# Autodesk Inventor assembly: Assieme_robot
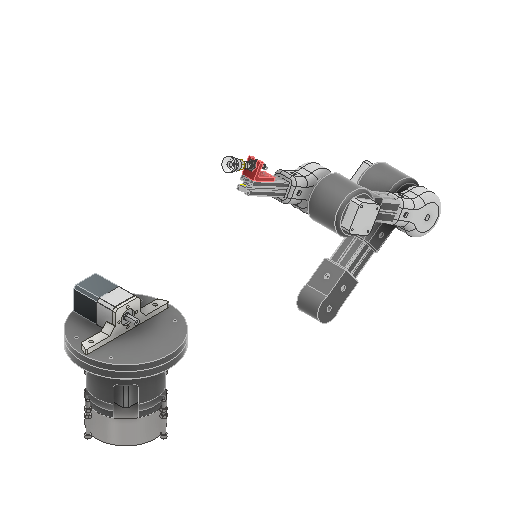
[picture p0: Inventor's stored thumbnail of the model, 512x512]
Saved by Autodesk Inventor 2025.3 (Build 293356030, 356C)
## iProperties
Created: 2026-03
Part Number: Assieme_robot
Document SubType Name: Assembly
Designer: R5800u
Author: R5800u
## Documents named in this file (19)
- C:\Users\R5800u\Desktop\robot_riduttore_cicloidale3\Workgroups\NotInProject\Assieme_robot.iam
- C:\Users\R5800u\Desktop\robot_riduttore_cicloidale3\Workgroups\NotInProject\riduttore_cicloidale_nema17-47mm.iam
- C:\Users\R5800u\Desktop\robot_riduttore_cicloidale3\Workgroups\NotInProject\braccio1.ipt
- C:\Users\R5800u\Desktop\robot_riduttore_cicloidale3\Workgroups\NotInProject\tslot-20x20-100mm.ipt
- C:\Users\R5800u\Desktop\robot_riduttore_cicloidale3\Workgroups\NotInProject\riduttore_cicloidale_nema17-40mm.iam
- C:\Users\R5800u\Desktop\robot_riduttore_cicloidale3\Workgroups\NotInProject\base_ferro.ipt
- C:\Users\R5800u\Desktop\robot_riduttore_cicloidale3\Workgroups\NotInProject\ISO 104 - 1 11 50 x 70 x 14.ipt
- C:\Users\R5800u\Desktop\robot_riduttore_cicloidale3\Workgroups\NotInProject\blocco_base.ipt
- C:\Users\R5800u\Desktop\robot_riduttore_cicloidale3\Workgroups\NotInProject\disco_base1.ipt
- C:\Users\R5800u\Desktop\robot_riduttore_cicloidale3\Workgroups\NotInProject\disco_base2.ipt
- C:\Users\R5800u\Desktop\robot_riduttore_cicloidale3\Workgroups\NotInProject\staffa_nema.ipt
- C:\Users\R5800u\Documents\Inventor\Content Center Files\R2025\it-IT\AS 1112 (2)\AS 1112 - M5  Tipo 5.ipt
- C:\Users\R5800u\Documents\Inventor\Content Center Files\R2025\it-IT\ANSI B18.3.1M(6)\ANSI B18.3.1M - M5x0,8 x 50(1).ipt
- C:\Users\R5800u\Desktop\robot_riduttore_cicloidale3\Workgroups\NotInProject\blocco_nema.ipt
- C:\Users\R5800u\Desktop\robot_riduttore_cicloidale3\Workgroups\NotInProject\blocco_albero_nema.ipt
- C:\Users\R5800u\Desktop\robot_riduttore_cicloidale3\Workgroups\NotInProject\ventosa_20mm.iam
- C:\Users\R5800u\Documents\Inventor\Content Center Files\R2025\it-IT\AS 1420\AS 1420 - 1973 - M3 x 16.ipt
- C:\Users\R5800u\Documents\Inventor\Content Center Files\R2025\it-IT\AS 1112 (2)\AS 1112 - M4  Tipo 5.ipt
- C:\Users\R5800u\Desktop\robot_riduttore_cicloidale3\Workgroups\NotInProject\Assieme_frame_tslot.iam
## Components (37 placed, 18 different names)
1. riduttore_cicloidale_nema17-47mm:1 [sub-assembly]
2. braccio1:1 — Coincidente:7, Angolo:1, Coincidente:10, Coincidente:11, Allineato:4, Coincidente:56, Coincidente:59
3. tslot-20x20-100mm:1 — Coincidente:10, Coincidente:11, Coincidente:37, Allineato:9, Coincidente:38, Coincidente:56, Coincidente:57, Coincidente:58
4. riduttore_cicloidale_nema17-40mm:1 [sub-assembly] — Coincidente:13, Allineato:3, Angolo:2, Coincidente:16, Coincidente:18
5. base_ferro:1
6. UNI ISO 104 1 11 50 x 70 x 14:1 — Coincidente:14, Coincidente:15
7. blocco_base:1
8. disco_base1:1 — Coincidente:16, Coincidente:17, Coincidente:19, Angolo:6
9. disco_base2:1 — Coincidente:18, Coincidente:19, Angolo:3, Coincidente:20
10. staffa_nema:1 — Coincidente:24, Coincidente:25, Allineato:6
11. AS 1112 (2) - Metrico M5  Tipo 5:5
12. AS 1112 (2) - Metrico M5  Tipo 5:6
13. AS 1112 (2) - Metrico M5  Tipo 5:7
14. AS 1112 (2) - Metrico M5  Tipo 5:8
15. Vite forgiata a testa incassata - Metrico M5x0,8 x 50:1 — Coincidente:30
16. Vite forgiata a testa incassata - Metrico M5x0,8 x 50:2 — Coincidente:32
17. Vite forgiata a testa incassata - Metrico M5x0,8 x 50:3 — Coincidente:34
18. Vite forgiata a testa incassata - Metrico M5x0,8 x 50:4 — Coincidente:36
19. blocco_nema:1 — Coincidente:37, Allineato:9, Coincidente:38, Coincidente:39, Angolo:4, Allineato:10, Coincidente:41
20. riduttore_cicloidale_nema17-40mm:2 [sub-assembly] — Coincidente:39, Angolo:4, Allineato:10, Coincidente:40
21. blocco_albero_nema:1 — Coincidente:40, Coincidente:41, Coincidente:42, Coincidente:43, Coincidente:44
22. tslot-20x20-100mm:2 — Coincidente:42, Coincidente:43, Coincidente:44, Coincidente:45, Allineato:11, Coincidente:46, Coincidente:60, Coincidente:61
23. blocco_nema:2 — Coincidente:45, Allineato:11, Coincidente:46, Coincidente:47, Angolo:5, Coincidente:48, Coincidente:50, Coincidente:62
24. riduttore_cicloidale_nema17-40mm:3 [sub-assembly] — Coincidente:47, Angolo:5, Coincidente:48, Coincidente:49
25. blocco_albero_nema:2 — Coincidente:49, Coincidente:50, Coincidente:51, Coincidente:52, Coincidente:53, Coincidente:55
26. ventosa_20mm:1 [sub-assembly] — Coincidente:51, Coincidente:52, Coincidente:53
27. AS 1420 - Metrico M3 x 16:1 — Coincidente:55
28. AS 1112 (2) - Metrico M4  Tipo 5:1
29. AS 1112 (2) - Metrico M4  Tipo 5:2
30. AS 1112 (2) - Metrico M4  Tipo 5:3
31. AS 1112 (2) - Metrico M4  Tipo 5:4
32. Assieme_frame_tslot:1 [sub-assembly] — Coincidente:57, Coincidente:58, Coincidente:59
33. Assieme_frame_tslot:2 [sub-assembly] — Coincidente:60, Coincidente:61, Coincidente:62
34. AS 1112 (2) - Metrico M5  Tipo 5:1
35. AS 1112 (2) - Metrico M5  Tipo 5:2
36. AS 1112 (2) - Metrico M5  Tipo 5:3
37. AS 1112 (2) - Metrico M5  Tipo 5:4
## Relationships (54: Mate 42, Angle 6, Flush 6)
- Coincidente:7 [Mate]: braccio1:1
- Angolo:1 [Angle]: braccio1:1
- Coincidente:10 [Mate]: braccio1:1 ↔ tslot-20x20-100mm:1
- Coincidente:11 [Mate]: braccio1:1 ↔ tslot-20x20-100mm:1
- Coincidente:13 [Mate]: riduttore_cicloidale_nema17-40mm:1
- Allineato:3 [Flush]: riduttore_cicloidale_nema17-40mm:1
- Coincidente:14 [Mate]: UNI ISO 104 1 11 50 x 70 x 14:1
- Coincidente:15 [Mate]: UNI ISO 104 1 11 50 x 70 x 14:1
- Angolo:2 [Angle]: riduttore_cicloidale_nema17-40mm:1
- Coincidente:16 [Mate]: riduttore_cicloidale_nema17-40mm:1 ↔ disco_base1:1
- Coincidente:17 [Mate]: disco_base1:1
- Coincidente:18 [Mate]: riduttore_cicloidale_nema17-40mm:1 ↔ disco_base2:1
- Coincidente:19 [Mate]: disco_base1:1 ↔ disco_base2:1
- Angolo:3 [Angle]: disco_base2:1
- Coincidente:20 [Mate]: disco_base2:1
- Allineato:4 [Flush]: braccio1:1
- Coincidente:24 [Mate]: staffa_nema:1
- Coincidente:25 [Mate]: staffa_nema:1
- Allineato:6 [Flush]: staffa_nema:1
- Coincidente:30 [Mate]: Vite forgiata a testa incassata - Metrico M5x0,8 x 50:1
- Coincidente:32 [Mate]: Vite forgiata a testa incassata - Metrico M5x0,8 x 50:2
- Coincidente:34 [Mate]: Vite forgiata a testa incassata - Metrico M5x0,8 x 50:3
- Coincidente:36 [Mate]: Vite forgiata a testa incassata - Metrico M5x0,8 x 50:4
- Coincidente:37 [Mate]: tslot-20x20-100mm:1 ↔ blocco_nema:1
- Allineato:9 [Flush]: tslot-20x20-100mm:1 ↔ blocco_nema:1
- Coincidente:38 [Mate]: tslot-20x20-100mm:1 ↔ blocco_nema:1
- Coincidente:39 [Mate]: blocco_nema:1 ↔ riduttore_cicloidale_nema17-40mm:2
- Angolo:4 [Angle]: blocco_nema:1 ↔ riduttore_cicloidale_nema17-40mm:2
- Allineato:10 [Flush]: blocco_nema:1 ↔ riduttore_cicloidale_nema17-40mm:2
- Coincidente:40 [Mate]: riduttore_cicloidale_nema17-40mm:2 ↔ blocco_albero_nema:1
- Coincidente:41 [Mate]: blocco_nema:1 ↔ blocco_albero_nema:1
- Coincidente:42 [Mate]: blocco_albero_nema:1 ↔ tslot-20x20-100mm:2
- Coincidente:43 [Mate]: blocco_albero_nema:1 ↔ tslot-20x20-100mm:2
- Coincidente:44 [Mate]: blocco_albero_nema:1 ↔ tslot-20x20-100mm:2
- Coincidente:45 [Mate]: tslot-20x20-100mm:2 ↔ blocco_nema:2
- Allineato:11 [Flush]: tslot-20x20-100mm:2 ↔ blocco_nema:2
- Coincidente:46 [Mate]: tslot-20x20-100mm:2 ↔ blocco_nema:2
- Coincidente:47 [Mate]: blocco_nema:2 ↔ riduttore_cicloidale_nema17-40mm:3
- Angolo:5 [Angle]: blocco_nema:2 ↔ riduttore_cicloidale_nema17-40mm:3
- Coincidente:48 [Mate]: blocco_nema:2 ↔ riduttore_cicloidale_nema17-40mm:3
- Coincidente:49 [Mate]: riduttore_cicloidale_nema17-40mm:3 ↔ blocco_albero_nema:2
- Coincidente:50 [Mate]: blocco_nema:2 ↔ blocco_albero_nema:2
- Coincidente:51 [Mate]: blocco_albero_nema:2 ↔ ventosa_20mm:1
- Coincidente:52 [Mate]: blocco_albero_nema:2 ↔ ventosa_20mm:1
- Coincidente:53 [Mate]: blocco_albero_nema:2 ↔ ventosa_20mm:1
- Coincidente:55 [Mate]: blocco_albero_nema:2 ↔ AS 1420 - Metrico M3 x 16:1
- Angolo:6 [Angle]: disco_base1:1
- Coincidente:56 [Mate]: braccio1:1 ↔ tslot-20x20-100mm:1
- Coincidente:57 [Mate]: tslot-20x20-100mm:1 ↔ Assieme_frame_tslot:1
- Coincidente:58 [Mate]: tslot-20x20-100mm:1 ↔ Assieme_frame_tslot:1
- Coincidente:59 [Mate]: braccio1:1 ↔ Assieme_frame_tslot:1
- Coincidente:60 [Mate]: tslot-20x20-100mm:2 ↔ Assieme_frame_tslot:2
- Coincidente:61 [Mate]: tslot-20x20-100mm:2 ↔ Assieme_frame_tslot:2
- Coincidente:62 [Mate]: blocco_nema:2 ↔ Assieme_frame_tslot:2
